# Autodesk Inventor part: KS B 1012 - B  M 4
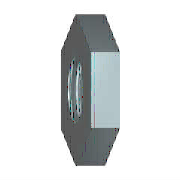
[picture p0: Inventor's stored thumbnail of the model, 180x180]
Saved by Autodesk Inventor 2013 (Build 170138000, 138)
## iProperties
Created: 2012-02
Part Number: KS B 1012 - B  M 4
Material: 강철, 연강
Description: 6각 너트 및 6각 가는 너트 - 모따기 안된
Document SubType Name: Modeling
Standard: KS B 1012
Designer: KYOUNG IL JANG
Standards Organization: KS
Language: ko-KR
Size Designation: B  M 4
Categories: <MemberInstance><Categories><Category DisplayName="조임쇠" InternalName="e4da775c-781d-43d5-af7c-5136215cf5a6" Mnemonic="FSTN"><Category DisplayName="너트" InternalN
Density: 7.86 g/cm^3
Mass: 0.583893 g
Surface Area: 1.40992 cm^2
Volume: 0.0742867 cm^3
IsCustomPart: 0
Author: KYOUNG IL JANG
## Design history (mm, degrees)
sketch "스케치1"
  geometry: L1 (2.021, -3.5)-(-2.021, -3.5); L2 (-2.021, -3.5)-(-4.041, 0); L3 (-4.041, 0)-(-2.021, 3.5); L4 (-2.021, 3.5)-(2.021, 3.5); L5 (2.021, 3.5)-(4.041, 0); L6 (4.041, 0)-(2.021, -3.5); 2 further points
  constraints: 12 end point, 1 coincident, 1 horizontal, 11 other
  dimensions: "d0" = 8.0829 distance of L5.end L2.end (= 1.1547 x SW)
extrude "본체" new body sketch "스케치1" distance "d1" = 2.2 (= KOH); taper "d2" = 0 deg
sketch "스케치2"
  geometry: 1 further point
hole "스레드" sketch "스케치2" diameter "d3" = 3.242; stored, may be unused: countersink angle "d7" = 82 deg, drill point angle "d9" = 118 deg; dims "d4" = 6, "d5" = 4, "d6" = 2, "d8" = 8
workaxis "Work Axis1"
workplane "Work Plane1"
body "Solid1"
chamfer "모따기2" distance "d12" = 0.37889 (= -0.5 x GD1 + 0.5 x NND); stored, may be unused: angle "d13" = 30 deg, second distance "d19" = 0.37889 (= -0.5 x GD1 + 0.5 x NND)
chamfer "모따기1" distance "d10" = 0.37889 (= -0.5 x GD1 + 0.5 x NND); stored, may be unused: angle "d11" = 30 deg, second distance "d18" = 0.37889 (= -0.5 x GD1 + 0.5 x NND)
other parameters: "NND" = 4 [user parameter; used in 4 equation terms], "KOH" = 2.2 [user parameter; used in 1 equation term], "SW" = 7 [user parameter; used in 2 equation terms], "GD1" = 3.24223 (computed from THREADDIA, PTC, TOA) [user parameter; used in 4 equation terms], "d15" = 0, "d17" = 0, "d20" = 0, "d21" = 0, "GUL" = 0.37889 (= 0.541266 x PTC) [user parameter], "TPU" = 14.28571 (computed from PTC) [user parameter], "THREADDIA" = 4 [user parameter; used in 1 equation term], "TOA" = 30 deg [user parameter; used in 1 equation term], "PTC" = 0.7 [user parameter; used in 4 equation terms], "E0" = 8.085 (= 1.155 x SW) [user parameter], "GAL" = 0.37889 (= 0.541266 x PTC) [user parameter]
